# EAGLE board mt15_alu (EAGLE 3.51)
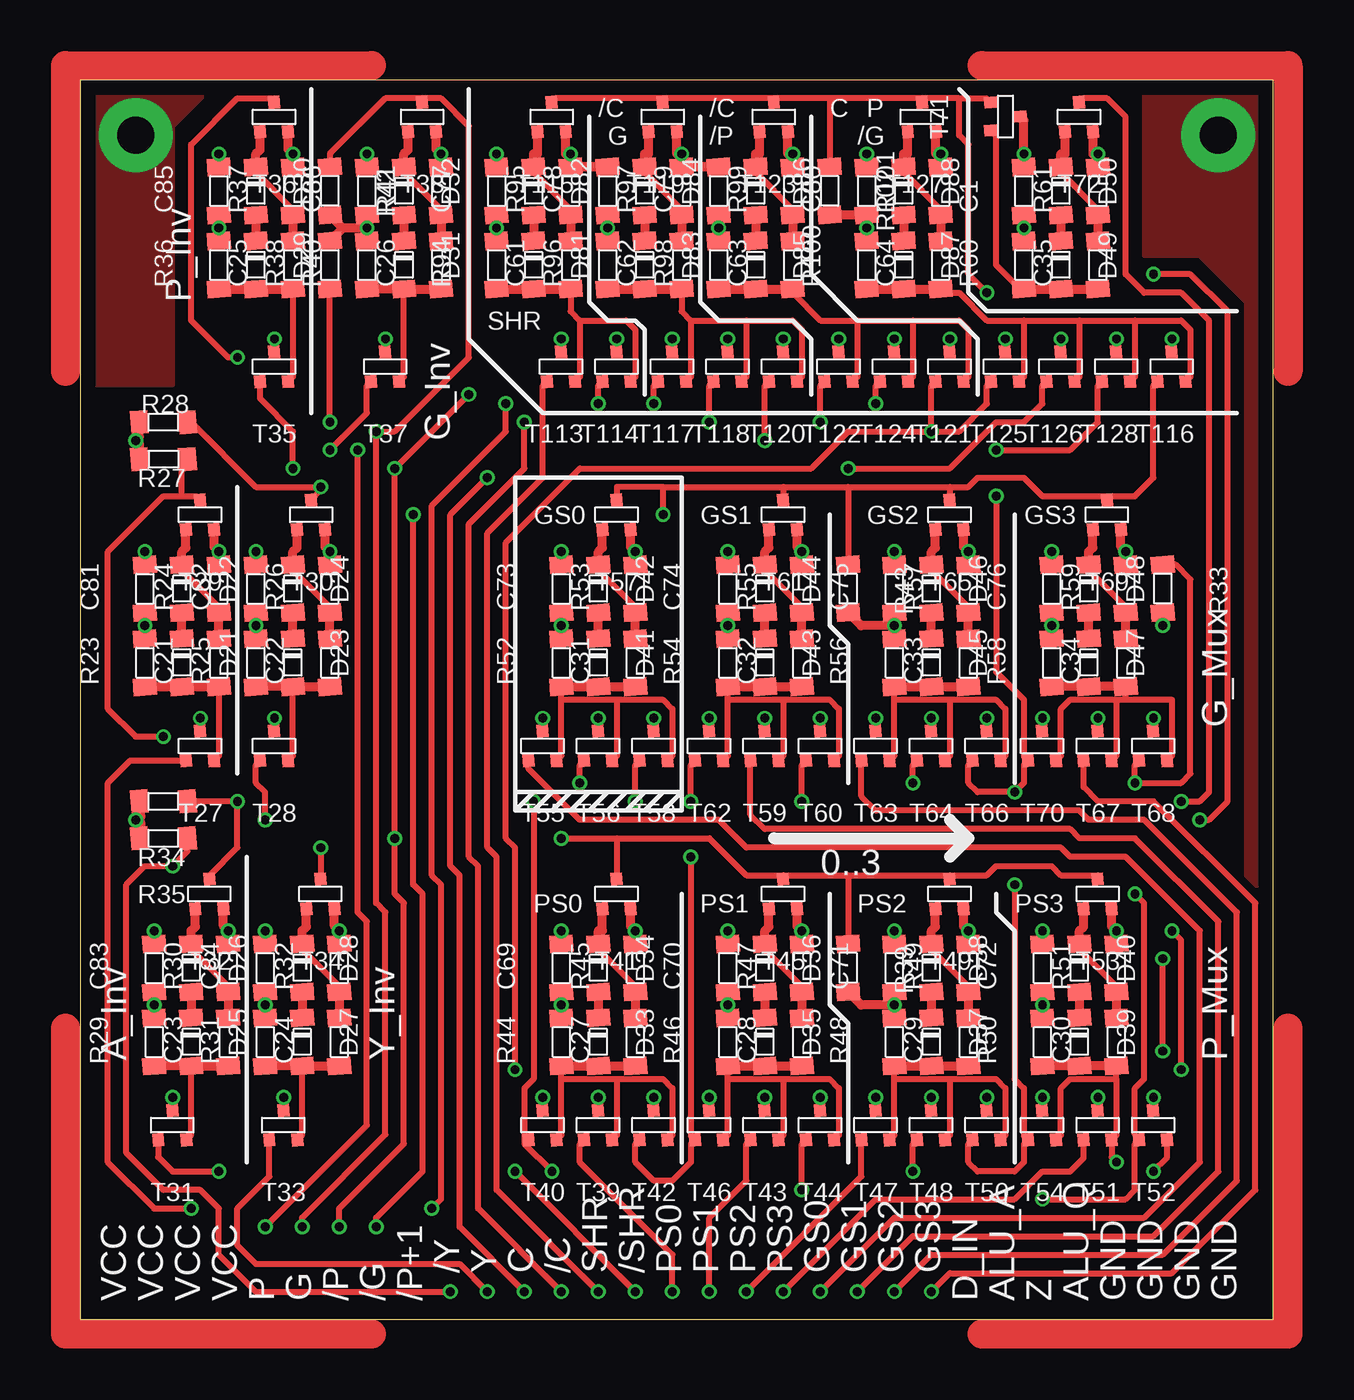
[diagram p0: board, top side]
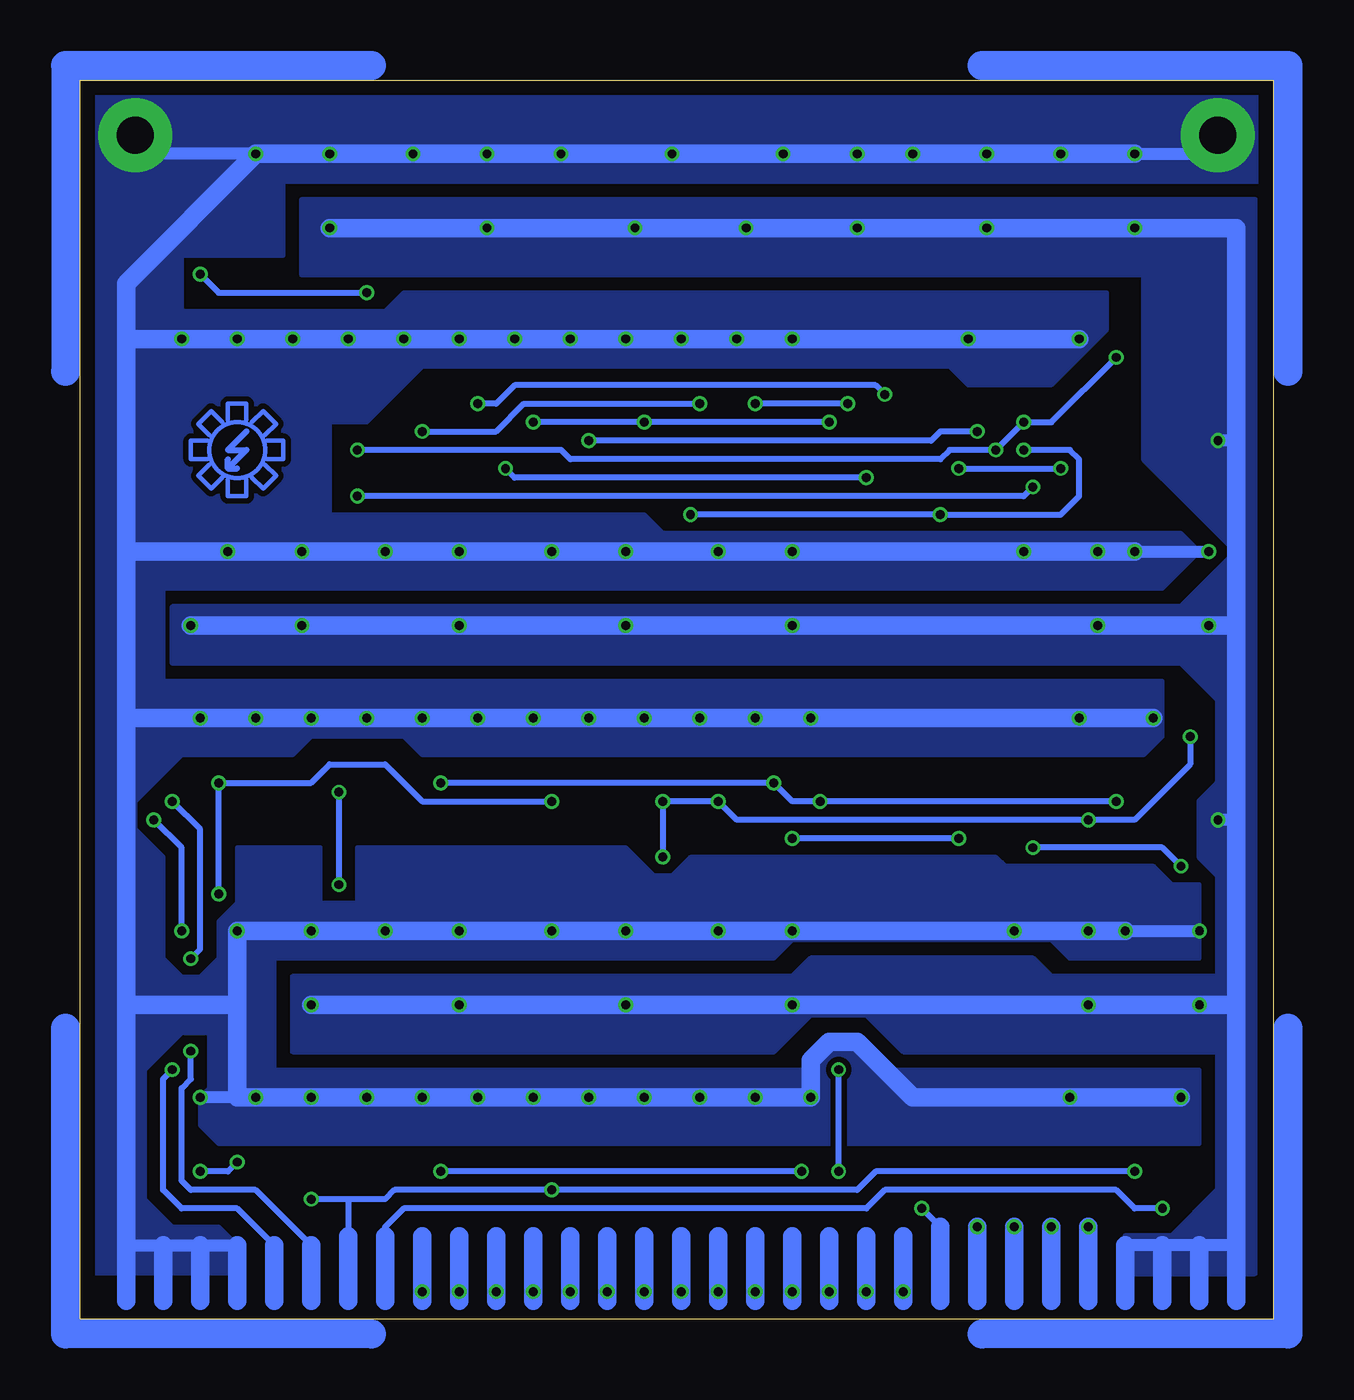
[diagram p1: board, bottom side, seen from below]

Size 81.89 x 85.08 mm. Coordinates in mm from the lower left corner, seen from the top.
Outline: 0,0 81.89,0 81.89,85.08 0,85.08 0,0
Copper layers used: Top, Bottom

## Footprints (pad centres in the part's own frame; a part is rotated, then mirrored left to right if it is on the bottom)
04 = smd 1.194 x 1.6 rotated 4.4:  1.651,0 | smd 1.194 x 1.6 rotated 4.3:  -1.651,0
04D = smd 1.194 x 1.6 rotated 4.3:  1.651,0 | smd 1.194 x 1.6 rotated 4.4:  -1.651,0
T-23 = smd 0.787 x 0.889 rotated 4.4:  0.991,1.016 | smd 0.787 x 0.889 rotated 4.3:  -0.94,1.016 | smd 0.787 x 0.889 rotated 4.5:  0.025,-1.016

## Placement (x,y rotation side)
C1  100n  [04]  64.77,77.47 90 top
C21  1n  [04]  9.53,45.09 90 top
C22  1n  [04]  17.14,45.09 90 top
C23  1n  [04]  10.16,19.05 90 top
C24  1n  [04]  17.78,19.05 90 top
C25  1n  [04]  14.61,72.39 90 top
C26  1n  [04]  24.77,72.39 90 top
C27  1n  [04]  38.1,19.05 90 top
C28  1n  [04]  49.53,19.05 90 top
C29  1n  [04]  60.96,19.05 90 top
C30  1n  [04]  71.12,19.05 90 top
C31  1n  [04]  38.1,45.09 90 top
C32  1n  [04]  49.53,45.09 90 top
C33  1n  [04]  60.96,45.09 90 top
C34  1n  [04]  71.75,45.09 90 top
C35  1n  [04]  69.85,72.39 90 top
C61  1n  [04]  33.66,72.39 90 top
C62  1n  [04]  41.27,72.39 90 top
C63  1n  [04]  48.9,72.39 90 top
C64  1n  [04]  59.05,72.39 90 top
C69  100n  [04]  33.02,24.13 90 top
C70  100n  [04]  44.45,24.13 90 top
C71  100n  [04]  55.88,24.13 90 top
C72  100n  [04]  66.04,24.13 90 top
C73  100n  [04]  33.02,50.16 90 top
C74  100n  [04]  44.45,50.16 90 top
C75  100n  [04]  55.88,50.16 90 top
C76  100n  [04]  66.67,50.16 90 top
C77  100n  [04]  28.57,77.47 90 top
C78  100n  [04]  36.2,77.47 90 top
C79  100n  [04]  43.81,77.47 90 top
C80  100n  [04]  53.98,77.47 90 top
C81  100n  [04]  4.45,50.16 90 top
C82  100n  [04]  12.06,50.16 90 top
C83  100n  [04]  5.08,24.13 90 top
C84  100n  [04]  12.7,24.13 90 top
C85  100n  [04]  9.53,77.47 90 top
C86  100n  [04]  19.68,77.47 90 top
D21  1N4148  [04D]  6.99,45.09 270 top
D22  1N4148  [04D]  6.99,50.16 270 top
D23  1N4148  [04D]  14.61,45.09 270 top
D24  1N4148  [04D]  14.61,50.16 270 top
D25  1N4148  [04D]  7.62,19.05 270 top
D26  1N4148  [04D]  7.62,24.13 270 top
D27  1N4148  [04D]  15.24,19.05 270 top
D28  1N4148  [04D]  15.24,24.13 270 top
D29  1N4148  [04D]  12.06,72.39 270 top
D30  1N4148  [04D]  12.06,77.47 270 top
D31  1N4148  [04D]  22.23,72.39 270 top
D32  1N4148  [04D]  22.23,77.47 270 top
D33  1N4148  [04D]  35.56,19.05 270 top
D34  1N4148  [04D]  35.56,24.13 270 top
D35  1N4148  [04D]  46.99,19.05 270 top
D36  1N4148  [04D]  46.99,24.13 270 top
D37  1N4148  [04D]  58.42,19.05 270 top
D38  1N4148  [04D]  58.42,24.13 270 top
D39  1N4148  [04D]  68.58,19.05 270 top
D40  1N4148  [04D]  68.58,24.13 270 top
D41  1N4148  [04D]  35.56,45.09 270 top
D42  1N4148  [04D]  35.56,50.16 270 top
D43  1N4148  [04D]  46.99,45.09 270 top
D44  1N4148  [04D]  46.99,50.16 270 top
D45  1N4148  [04D]  58.42,45.09 270 top
D46  1N4148  [04D]  58.42,50.16 270 top
D47  1N4148  [04D]  69.22,45.09 270 top
D48  1N4148  [04D]  69.22,50.16 270 top
D49  1N4148  [04D]  67.31,72.39 270 top
D50  1N4148  [04D]  67.31,77.47 270 top
D81  1N4148  [04D]  31.11,72.39 270 top
D82  1N4148  [04D]  31.11,77.47 270 top
D83  1N4148  [04D]  38.73,72.39 270 top
D84  1N4148  [04D]  38.73,77.47 270 top
D85  1N4148  [04D]  46.35,72.39 270 top
D86  1N4148  [04D]  46.35,77.47 270 top
D87  1N4148  [04D]  56.52,72.39 270 top
D88  1N4148  [04D]  56.52,77.47 270 top
R23  390  [04]  4.45,45.09 90 top
R24  820  [04]  9.53,50.16 90 top
R25  390  [04]  12.06,45.09 90 top
R26  820  [04]  17.14,50.16 90 top
R27  330  [04]  5.71,61.59 180 top
R28  330  [04]  5.71,59.05 0 top
R29  390  [04]  5.08,19.05 90 top
R30  820  [04]  10.16,24.13 90 top
R31  390  [04]  12.7,19.05 90 top
R32  820  [04]  17.78,24.13 90 top
R33  330  [04]  74.3,50.16 270 top
R34  330  [04]  5.71,35.56 180 top
R35  330  [04]  5.71,33.02 180 top
R36  390  [04]  9.53,72.39 90 top
R37  820  [04]  14.61,77.47 90 top
R38  330  [04]  17.14,72.39 90 top
R39  330  [04]  52.7,24.13 270 top
R40  390  [04]  19.68,72.39 90 top
R41  820  [04]  24.77,77.47 90 top
R42  330  [04]  17.14,77.47 270 top
R43  330  [04]  52.7,50.16 270 top
R44  390  [04]  33.02,19.05 90 top
R45  820  [04]  38.1,24.13 90 top
R46  390  [04]  44.45,19.05 90 top
R47  820  [04]  49.53,24.13 90 top
R48  390  [04]  55.88,19.05 90 top
R49  820  [04]  60.96,24.13 90 top
R50  390  [04]  66.04,19.05 90 top
R51  820  [04]  71.12,24.13 90 top
R52  390  [04]  33.02,45.09 90 top
R53  820  [04]  38.1,50.16 90 top
R54  390  [04]  44.45,45.09 90 top
R55  820  [04]  49.53,50.16 90 top
R56  390  [04]  55.88,45.09 90 top
R57  820  [04]  60.96,50.16 90 top
R58  390  [04]  66.67,45.09 90 top
R59  820  [04]  71.75,50.16 90 top
R60  390  [04]  64.77,72.39 90 top
R61  820  [04]  69.85,77.47 90 top
R94  390  [04]  28.57,72.39 90 top
R95  820  [04]  33.66,77.47 90 top
R96  390  [04]  36.2,72.39 90 top
R97  820  [04]  41.27,77.47 90 top
R98  390  [04]  43.81,72.39 90 top
R99  820  [04]  48.9,77.47 90 top
R100  390  [04]  53.98,72.39 90 top
R101  820  [04]  59.05,77.47 90 top
R102  330  [04]  51.44,77.47 270 top
T27  BC857  [T-23]  8.26,39.37 180 top
T28  BC857  [T-23]  13.34,39.37 180 top
T29  BC847  [T-23]  8.26,55.24 180 top
T30  BC847  [T-23]  15.88,55.24 180 top
T31  BC857  [T-23]  6.35,13.34 180 top
T32  BC847  [T-23]  8.89,29.21 180 top
T33  BC857  [T-23]  13.97,13.34 180 top
T34  BC847  [T-23]  16.51,29.21 180 top
T35  BC857  [T-23]  13.34,65.41 180 top
T36  BC847  [T-23]  13.34,82.55 180 top
T37  BC857  [T-23]  20.95,65.41 180 top
T38  BC847  [T-23]  23.5,82.55 180 top
T39  BC857  [T-23]  35.56,13.34 180 top
T40  BC857  [T-23]  31.75,13.34 180 top
T41  BC847  [T-23]  36.83,29.21 180 top
T42  BC857  [T-23]  39.37,13.34 180 top
T43  BC857  [T-23]  46.99,13.34 180 top
T44  BC857  [T-23]  50.8,13.34 180 top
T45  BC847  [T-23]  48.26,29.21 180 top
T46  BC857  [T-23]  43.18,13.34 180 top
T47  BC857  [T-23]  54.61,13.34 180 top
T48  BC857  [T-23]  58.42,13.34 180 top
T49  BC847  [T-23]  59.69,29.21 180 top
T50  BC857  [T-23]  62.23,13.34 180 top
T51  BC857  [T-23]  69.85,13.34 180 top
T52  BC857  [T-23]  73.66,13.34 180 top
T53  BC847  [T-23]  69.85,29.21 180 top
T54  BC857  [T-23]  66.04,13.34 180 top
T55  BC857  [T-23]  31.75,39.37 180 top
T56  BC857  [T-23]  35.56,39.37 180 top
T57  BC847  [T-23]  36.83,55.24 180 top
T58  BC857  [T-23]  39.37,39.37 180 top
T59  BC857  [T-23]  46.99,39.37 180 top
T60  BC857  [T-23]  50.8,39.37 180 top
T61  BC847  [T-23]  48.26,55.24 180 top
T62  BC857  [T-23]  43.18,39.37 180 top
T63  BC857  [T-23]  54.61,39.37 180 top
T64  BC857  [T-23]  58.42,39.37 180 top
T65  BC847  [T-23]  59.69,55.24 180 top
T66  BC857  [T-23]  62.23,39.37 180 top
T67  BC857  [T-23]  69.85,39.37 180 top
T68  BC857  [T-23]  73.66,39.37 180 top
T69  BC847  [T-23]  70.48,55.24 180 top
T70  BC857  [T-23]  66.04,39.37 180 top
T71  BC857  [T-23]  63.5,82.55 90 top
T72  BC847  [T-23]  68.58,82.55 180 top
T113  BC857  [T-23]  33.02,65.41 180 top
T114  BC857  [T-23]  36.83,65.41 180 top
T115  BC847  [T-23]  32.38,82.55 180 top
T116  BC857  [T-23]  74.93,65.41 180 top
T117  BC857  [T-23]  40.64,65.41 180 top
T118  BC857  [T-23]  44.45,65.41 180 top
T119  BC847  [T-23]  40.01,82.55 180 top
T120  BC857  [T-23]  48.26,65.41 180 top
T121  BC857  [T-23]  59.69,65.41 180 top
T122  BC857  [T-23]  52.07,65.41 180 top
T123  BC847  [T-23]  47.62,82.55 180 top
T124  BC857  [T-23]  55.88,65.41 180 top
T125  BC857  [T-23]  63.5,65.41 180 top
T126  BC857  [T-23]  67.31,65.41 180 top
T127  BC847  [T-23]  57.78,82.55 180 top
T128  BC857  [T-23]  71.12,65.41 180 top
U$1  []  71.12,59.69 0 bottom

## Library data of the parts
C1 C21-C35 C61-C64 C69-C86 D21-D50 D81-D88 R23-R61 R94-R102 = DISCRETE
T27 T28 T31 T33 T35 T37 T39 T40 T42-T44 T46-T48 T50-T52 T54-T56 T58-T60 T62-T64 T66-T68 T70 T71 T113 T114 T116-T118 T120-T122 T124-T126 T128 = PNP
T29 T30 T32 T34 T36 T38 T41 T45 T49 T53 T57 T61 T65 T69 T72 T115 T119 T123 T127 = NPN
U$1 = TAF

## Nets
!ALU_A: R34. T32. T40. T48. T56. T64.
!ALU_D: R28. T28. T29. T42. T46. T58. T62.
!C: T118. T122.
!G: R43. T37. T57. T61. T65. T69. T116.
!P: R39. T35. T41. T45. T49. T53. T124.
!P+1: T114.
!SHR: T117. T121. T125.
!Y: R35. T34.
ALU_A: R33. T31. T44. T52. T60. T68.
ALU_D: R27. T30. T50. T54. T66. T70.
ALU_Q: R102. T71. T115. T119. T123. T127.
C: T126.
D_IN: T27.
G: R42. T38. T120.
GND: C1. C69. C70. C71. C72. C73. C74. C75. C76. C77. C78. C79. C80. C81. C82. C83. C84. C85. C86. R24. R26. R30. R32. R37. R41. R45. R47. R49. R51. R53. R55. R57. R59. R61. R95. R97. R99. R101. T27. T28. T29. T30. T31. T32. T33. T34. T35. T36. T37. T38. T39. T40. T41. T42. T43. T44. T45. T46. T47. T48. T49. T50. T51. T52. T53. T54. T55. T56. T57. T58. T59. T60. T61. T62. T63. T64. T65. T66. T67. T68. T69. T70. T71. T72. T113. T114. T115. T116. T117. T118. T119. T120. T121. T122. T123. T124. T125. T126. T127. T128.
GS0: T55.
GS1: T59.
GS2: T63.
GS3: T67.
N$45: C22. D23. R25. T28.
N$46: C21. D21. R23. T27.
N$47: D21. D22.
N$48: C21. D22. R24. T29.
N$49: D23. D24.
N$50: C22. D24. R26. T30.
N$51: C23. D25. R29. T31.
N$52: D25. D26.
N$53: C23. D26. R30. T32.
N$54: C24. D27. R31. T33.
N$55: D27. D28.
N$56: C24. D28. R32. T34.
N$57: C25. D29. R36. T35.
N$58: D29. D30.
N$59: C25. D30. R37. T36.
N$60: C26. D31. R40. T37.
N$61: D31. D32.
N$62: C26. D32. R41. T38.
N$63: C27. D33. R44. T39. T40. T42.
N$64: D33. D34.
N$65: C27. D34. R45. T41.
N$66: C28. D35. R46. T43. T44. T46.
N$67: D35. D36.
N$68: C28. D36. R47. T45.
N$69: C29. D37. R48. T47. T48. T50.
N$70: D37. D38.
N$71: C29. D38. R49. T49.
N$72: C30. D39. R50. T51. T52. T54.
N$73: D39. D40.
N$74: C30. D40. R51. T53.
N$75: C31. D41. R52. T55. T56. T58.
N$76: D41. D42.
N$77: C31. D42. R53. T57.
N$78: C32. D43. R54. T59. T60. T62.
N$79: D43. D44.
N$80: C32. D44. R55. T61.
N$81: C33. D45. R56. T63. T64. T66.
N$82: D45. D46.
N$83: C33. D46. R57. T65.
N$84: C34. D47. R58. T67. T68. T70.
N$85: D47. D48.
N$86: C34. D48. R59. T69.
N$87: C35. D49. R60. T71.
N$92: D49. D50.
N$141: C61. D81. R94. T113. T114.
N$142: D81. D82.
N$143: C61. D82. R95. T115.
N$144: C62. D83. R96. T117. T118. T120.
N$145: D83. D84.
N$146: C62. D84. R97. T119.
N$147: C63. D85. R98. T121. T122. T124.
N$148: D85. D86.
N$149: C63. D86. R99. T123.
N$150: C64. D87. R100. T116. T125. T126. T128.
N$151: D87. D88.
N$152: C64. D88. R101. T127.
N$153: C35. D50. R61. T72.
P: R38. T36. T128.
PS0: T39.
PS1: T43.
PS2: T47.
PS3: T51.
SHR: T113.
VCC: C1. C69. C70. C71. C72. C73. C74. C75. C76. C77. C78. C79. C80. C81. C82. C83. C84. C85. C86. R23. R25. R27. R28. R29. R31. R33. R34. R35. R36. R38. R39. R40. R42. R43. R44. R46. R48. R50. R52. R54. R56. R58. R60. R94. R96. R98. R100. R102.
Y: T33.
Z: T72.

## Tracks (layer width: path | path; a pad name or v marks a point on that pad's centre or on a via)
!ALU_A  (via drill 0.61 pad 1.02)
  Top 0.406: 34.57,38.35 34.29,38.08 v34.29,36.83 | 57.43,38.35 57.15,38.08 v57.15,36.83 | 57.43,12.32 57.15,12.04 v57.15,10.16 | T32. 8.87,30.45 10.79,32.38 v10.79,35.56 R34. | 30.48,12.06 v32.38,10.16 | v31.11,35.56 31.11,16.51 30.48,15.88 30.48,12.06 | 30.76,12.32 30.73,12.32 30.48,12.06
  Bottom 0.406: v57.15,36.83 v34.29,36.83 33.02,35.56 v31.11,35.56 v10.79,35.56 | v32.38,10.16 v57.15,10.16
!ALU_D  (via drill 0.61 pad 1.02)
  Top 0.406: 42.19,38.35 41.91,38.08 v41.91,35.56 | 38.38,38.35 38.1,38.08 v38.1,35.56 | 12.34,38.35 12.06,38.08 12.06,36.83 12.7,36.2 v12.7,34.29 | 38.38,12.32 38.1,12.04 38.1,10.79 39.37,9.53 40.64,9.53 41.91,10.79 41.91,12.04 42.19,12.32 41.91,12.6 v41.91,31.75 | v5.71,40.01 3.81,40.01 1.91,41.91 1.91,52.7 5.71,56.52 6.99,56.52 | T29. 7.98,56.52 6.99,56.52 | 7.37,59.05 6.99,58.67 6.99,56.52
  Bottom 0.406: v41.91,31.75 v41.91,35.56 v38.1,35.56 36.83,34.29 v12.7,34.29 9.53,34.29 5.71,38.1 v5.71,40.01
!C  (via drill 0.61 pad 1.02)
  Top 0.406: 43.46,64.39 43.18,64.11 v43.18,61.59 | 51.08,64.39 50.8,64.11 v50.8,61.59 | v33.02,1.91 27.3,7.62 27.3,31.11 26.67,31.75 26.67,54.61 30.48,58.42 v30.48,61.59
  Bottom 0.406: v50.8,61.59 v43.18,61.59 v30.48,61.59
  Bottom 1.27: 33.02,1.27 v33.02,1.91 33.02,5.71
!G  (via drill 0.61 pad 1.02)
  Top 0.406: 48.26,57.15 52.7,57.15 | 52.7,57.15 59.69,57.15 | 40.01,57.15 36.83,57.15 36.83,56.29 T57. | v40.01,55.24 40.01,57.15 | 40.01,57.15 48.26,57.15 | T61. 48.26,56.29 48.26,57.15 | T65. 59.69,56.29 59.69,57.15 | T69. 70.48,56.29 70.48,56.52 | 59.69,57.15 60.96,57.15 61.59,57.78 64.77,57.78 66.04,56.52 70.48,56.52 | 73.94,64.39 73.66,64.11 73.66,57.78 72.39,56.52 70.48,56.52 | v20.32,6.35 20.32,6.99 23.5,10.16 23.5,29.21 22.86,29.84 v22.86,55.24 | 52.7,57.15 R43. | 19.96,64.39 19.68,64.11 19.68,62.23 v17.14,59.69
  Bottom 0.406: v40.01,55.24 v22.86,55.24 14.61,55.24 13.34,56.52 13.34,59.05 13.97,59.69 v17.14,59.69
  Bottom 1.27: 20.32,1.27 v20.32,6.35
!P  (via drill 0.61 pad 1.02)
  Top 0.406: T41. 36.83,30.25 36.83,33.02 | T53. 69.85,30.25 69.85,30.48 67.31,30.48 66.67,31.11 62.87,31.11 62.23,30.48 59.69,30.48 | 36.83,33.02 43.18,33.02 45.72,30.48 48.26,30.48 | 48.26,30.48 52.7,30.48 | 52.7,30.48 59.69,30.48 | T49. 59.69,30.25 59.69,30.48 | T45. 48.26,30.25 48.26,30.48 | 52.7,30.48 R39. | v17.78,6.35 17.78,7.62 22.23,12.06 22.23,28.57 21.59,29.21 v21.59,33.02 v21.59,58.42 v26.67,63.5 | v33.02,33.02 36.83,33.02 | 12.34,64.49 12.34,64.39 12.34,63.22 14.61,60.96 v14.61,58.42 | 54.89,64.39 54.61,64.11 v54.61,62.87
  Bottom 0.406: v21.59,33.02 v33.02,33.02 | v21.59,58.42 v14.61,58.42 | v26.67,63.5 27.3,64.14 52.07,64.14 53.34,62.87 v54.61,62.87
  Bottom 1.27: 17.78,1.27 v17.78,6.35
!P+1  (via drill 0.61 pad 1.02)
  Top 0.406: v24.13,7.62 24.77,8.26 24.77,29.84 24.13,30.48 24.13,55.88 29.21,60.96 v29.21,62.87 | 35.56,64.11 35.84,64.39 | v35.56,62.87 35.56,64.11 | 35.56,64.11 35.56,64.14
  Bottom 0.406: 22.86,6.35 v24.13,7.62 | v29.21,62.87 v35.56,62.87
  Bottom 1.27: 22.86,1.27 22.86,6.35
!SHR  (via drill 0.61 pad 1.02)
  Top 0.406: 39.65,64.39 39.37,64.11 v39.37,62.87 | 58.7,64.39 58.42,64.11 v58.42,60.96 | 62.51,64.39 62.23,64.11 62.23,62.87 60.33,60.96 v58.42,60.96 | v29.84,10.16 v38.1,1.91 | v29.84,17.14 29.84,32.38 29.21,33.02 29.21,53.34 34.29,58.42 50.16,58.42 52.7,60.96 v58.42,60.96
  Bottom 0.406: v58.42,60.96 53.34,60.96 51.44,62.87 v39.37,62.87 | v29.84,10.16 v29.84,17.14
  Bottom 1.27: 38.1,1.27 v38.1,1.91 38.1,5.71
!Y  (via drill 0.61 pad 1.02)
  Top 0.406: T34. 16.51,30.25 v16.51,32.38 | v25.4,1.91 12.06,1.91 9.53,4.45 9.53,7.62 8.26,8.89 5.71,8.89 3.17,11.43 3.17,29.84 4.45,31.11 v6.35,31.11 7.37,32.13 R35.
  Bottom 0.406: v6.35,31.11 7.62,32.38 v16.51,32.38
  Bottom 1.27: 25.4,1.27 v25.4,1.91 25.4,5.71
ALU_A  (via drill 0.61 pad 1.02)
  Top 0.406: 49.81,38.35 49.53,38.08 v49.53,35.56 | 72.67,38.35 72.39,38.08 v72.39,36.83 75.56,36.83 76.2,37.47 76.2,50.8 75.18,51.82 R33. | 49.81,12.32 49.53,12.04 v49.53,8.89 | v66.04,8.26 71.75,8.26 72.39,8.89 72.39,12.04 72.67,12.32 72.67,12.42 72.39,12.7 72.39,15.88 73.03,16.51 73.03,28.57 v72.39,29.21 | v9.53,10.16 6.35,10.16 5.36,11.15 5.36,12.32
  Bottom 0.406: v49.53,35.56 58.42,35.56 60.96,38.1 64.77,38.1 66.04,36.83 v72.39,36.83 v72.39,29.21 | 63.5,8.26 60.96,8.26 60.33,8.89 v49.53,8.89 28.57,8.89 27.3,10.16 v9.53,10.16 | 63.5,8.26 v66.04,8.26 | 63.5,8.26 63.5,5.71
  Bottom 1.27: 63.5,5.71 63.5,1.27
ALU_D  (via drill 0.61 pad 1.02)
  Top 0.406: 61.24,38.35 60.96,38.08 60.96,36.83 61.59,36.2 v64.14,36.2 64.77,36.83 64.77,38.08 65.05,38.35 64.77,38.63 64.77,42.55 62.87,44.45 v62.87,56.52 | 61.24,12.32 60.96,12.04 60.96,10.79 61.59,10.16 64.14,10.16 64.77,10.79 64.77,12.04 65.05,12.32 64.77,12.6 64.77,15.88 64.14,16.51 v64.14,29.84 | R27. 7.62,61.59 12.06,57.15 v16.51,57.15 | v16.51,57.15 16.48,57.12 | T30. 16.51,56.92 v16.51,57.15
  Bottom 0.406: v64.14,36.2 v64.14,29.84 | v62.87,56.52 17.14,56.52 v16.51,57.15
ALU_Q  (via drill 0.61 pad 1.02)
  Top 0.406: T115. 32.61,83.82 40.01,83.82 | 47.62,83.82 40.01,83.82 | 51.44,83.82 47.62,83.82 | 51.44,83.82 R102. | T119. 40.01,83.59 40.01,83.82 | T123. 47.62,83.59 47.62,83.82 | 57.78,83.82 51.44,83.82 | T127. 57.76,83.8 57.78,83.82 | 60.33,83.82 57.78,83.82 | 60.33,83.82 60.33,81.28 60.96,80.64 60.96,71.75 v62.23,70.48 | 62.48,83.54 62.2,83.82 60.33,83.82 | v73.66,71.75 76.2,71.75 78.74,69.22 78.74,35.56 77.47,34.29 v76.83,34.29 | v74.93,26.67 75.56,26.04 v75.56,17.14
  Bottom 0.406: v62.23,70.48 72.39,70.48 v73.66,71.75 | v76.83,34.29 74.93,32.38 v74.93,26.67 | v75.56,17.14 76.2,16.51 76.2,8.89 74.93,7.62 71.12,7.62 68.58,5.08
  Bottom 1.27: 68.58,1.27 68.58,5.08
C  (via drill 0.61 pad 1.02)
  Top 0.406: v30.48,1.91 26.04,6.35 26.04,30.48 25.4,31.11 25.4,55.24 v27.94,57.78 | 66.32,64.39 66.04,64.11 66.04,62.87 64.77,61.59 62.87,61.59 59.69,58.42 v52.7,58.42
  Bottom 0.406: v27.94,57.78 52.07,57.78 v52.7,58.42
  Bottom 1.27: 30.48,1.27 v30.48,1.91 30.48,5.71
D_IN  (via drill 0.61 pad 1.02)
  Top 0.406: v7.62,7.62 5.08,7.62 1.91,10.79 1.91,36.83 3.43,38.35 7.26,38.35
  Bottom 0.406: 60.96,5.71 60.96,6.35 59.69,7.62 27.94,7.62 26.67,8.89 10.79,8.89 9.53,7.62 v7.62,7.62
  Bottom 1.27: 60.96,5.71 60.96,1.27
G  (via drill 0.61 pad 1.02)
  Top 0.406: 47.27,64.39 46.99,64.11 v46.99,60.33 | R42. 17.14,80.01 20.95,83.82 23.5,83.82 | T38. 23.5,83.59 23.5,83.82 | 23.5,83.82 24.77,83.82 26.67,81.92 26.67,66.04 21.59,60.96 v20.32,60.96 20.32,28.57 20.95,27.94 20.95,12.7 15.24,6.99 v15.24,6.35
  Bottom 0.406: v20.32,60.96 22.86,60.96 23.5,60.33 v46.99,60.33
  Bottom 1.27: 15.24,1.27 v15.24,6.35
GND  (via drill 0.61 pad 1.02, 2.54 pad 5.08)
  Top 0.61: 33.33,81.53 33.33,80.01 v33.66,80.01 33.66,79.12 | 40.95,81.53 40.95,80.01 v41.27,80.01 41.27,79.12 | 48.56,81.53 48.56,80.01 v48.9,80.01 48.9,79.12 | 59.05,79.12 v59.05,80.01 58.73,80.01 58.73,81.53 | 69.52,81.53 69.52,80.01 v69.85,80.01 69.85,79.12 | 64.77,79.12 v64.77,80.01 64.77,82.32 T71. | v28.57,80.01 28.57,79.12 | T113. 33.02,66.45 v33.02,67.31 | T114. 36.83,66.45 v36.83,67.31 | T117. 40.64,66.45 v40.64,67.31 | T118. 44.45,66.45 v44.45,67.31 | T120. 48.26,66.45 v48.26,67.31 | T121. 59.69,66.45 v59.69,67.31 | T122. 52.07,66.45 v52.07,67.31 | T124. 55.88,66.45 v55.88,67.31 | T116. 74.93,66.45 v74.93,67.31 | T128. 71.12,66.45 v71.12,67.31 | T126. 67.31,66.45 v67.31,67.31 | T125. 63.5,66.45 v63.5,67.31 | v33.02,52.7 33.02,51.82 | 37.77,54.23 37.77,53.03 v38.1,52.7 38.1,51.82 | v44.45,52.7 44.45,51.82 | 49.2,54.23 49.2,53.03 v49.53,52.7 49.53,51.82 | v55.88,52.7 55.88,51.82 | 60.63,54.23 60.63,53.03 v60.96,52.7 60.96,51.82 | 71.42,54.23 71.42,53.03 v71.75,52.7 71.75,51.82 | v66.67,52.7 66.67,51.82 | 37.77,28.19 37.77,27 v38.1,26.67 38.1,25.78 | 49.2,28.19 49.2,27 v49.53,26.67 49.53,25.78 | v44.45,26.67 44.45,25.78 | v33.02,26.67 33.02,25.78 | v55.88,26.67 55.88,25.78 | 60.63,28.19 60.63,27 v60.96,26.67 60.96,25.78 | 70.79,28.19 70.79,27 v71.12,26.67 71.12,25.78 | v66.04,26.67 66.04,25.78 | T55. 31.75,40.41 v31.75,41.27 | T56. 35.56,40.41 v35.56,41.27 | T58. 39.37,40.41 v39.37,41.27 | T62. 43.18,40.41 v43.18,41.27 | T59. 46.99,40.41 v46.99,41.27 | T60. 50.8,40.41 v50.8,41.27 | T63. 54.61,40.41 v54.61,41.27 | T64. 58.42,40.41 v58.42,41.27 | T66. 62.23,40.41 v62.23,41.27 | T68. 73.66,40.41 v73.66,41.27 | T70. 66.04,40.41 v66.04,41.27
  Top 0.61: T67. 69.85,40.41 v69.85,41.27 | T52. 73.66,14.38 v73.66,15.24 | T51. 69.85,14.38 v69.85,15.24 | T54. 66.04,14.38 v66.04,15.24 | T50. 62.23,14.38 v62.23,15.24 | T48. 58.42,14.38 v58.42,15.24 | T47. 54.61,14.38 v54.61,15.24 | T44. 50.8,14.38 v50.8,15.24 | T43. 46.99,14.38 v46.99,15.24 | T46. 43.18,14.38 v43.18,15.24 | T42. 39.37,14.38 v39.37,15.24 | 9.83,28.19 9.83,27 v10.16,26.67 10.16,25.78 | v5.08,26.67 5.08,25.78 | v12.7,26.67 12.7,25.78 | 17.45,28.19 17.45,27 v17.78,26.67 17.78,25.78 | v4.45,52.7 4.45,51.82 | 9.2,54.23 9.2,53.03 v9.53,52.7 9.53,51.82 | v12.06,52.7 12.06,51.82 | 16.82,54.23 16.82,53.03 v17.14,52.7 17.14,51.82 17.14,51.44 | 14.28,81.53 14.28,80.34 v14.61,80.01 14.61,79.12 | v9.53,80.01 9.53,79.12 | v19.68,80.01 19.68,79.12 | 24.43,81.53 24.43,80.34 v24.77,80.01 24.77,79.12 | T31. 6.35,14.38 v6.35,15.24 | T33. 13.97,14.38 v13.97,15.24 | T27. 8.26,40.41 v8.26,41.27 | T28. 13.34,40.41 v13.34,41.27 | T35. 13.34,66.45 v13.34,67.31 | T37. 20.95,66.45 v20.95,67.31 | T40. 31.75,14.38 v31.75,15.24 | T39. 35.56,14.38 v35.56,15.24
  Top 0.635: 33.66,79.12 36.2,79.12 | 41.27,79.12 43.81,79.12 | v53.98,80.01 53.98,79.12
  Bottom 0.813: 71.12,15.24 v73.66,15.24 | v10.16,26.67 v5.08,26.67 | v9.53,52.7 v4.45,52.7 | 78.74,5.08 76.2,5.08 73.66,5.08 71.12,5.08 | v69.85,80.01 76.83,80.01 v78.11,81.28 | v3.81,81.28 5.08,80.01 v9.53,80.01
  Bottom 1.27: 78.74,67.31 v74.93,67.31 v71.12,67.31 v67.31,67.31 v63.5,67.31 v59.69,67.31 v55.88,67.31 v52.07,67.31 v48.26,67.31 v44.45,67.31 v40.64,67.31 v36.83,67.31 v33.02,67.31 v20.95,67.31 v13.34,67.31 | 78.74,67.31 78.74,71.12 v69.85,80.01 v64.77,80.01 v59.05,80.01 v53.98,80.01 v48.9,80.01 v41.27,80.01 v33.66,80.01 v28.57,80.01 v24.77,80.01 v19.68,80.01 v14.61,80.01 v9.53,80.01 | 78.74,41.27 v73.66,41.27 v69.85,41.27 v66.04,41.27 v62.23,41.27 v58.42,41.27 v54.61,41.27 v50.8,41.27 v46.99,41.27 v43.18,41.27 v39.37,41.27 v35.56,41.27 v31.75,41.27 v13.34,41.27 v8.26,41.27 | 78.74,41.27 78.74,52.7 | 78.74,52.7 78.74,67.31 | 78.74,52.7 v71.75,52.7 v66.67,52.7 v60.96,52.7 v55.88,52.7 v49.53,52.7 v44.45,52.7 v38.1,52.7 v33.02,52.7 v17.14,52.7 v12.06,52.7 v9.53,52.7 | 78.74,21.59 78.74,41.27 | v10.16,26.67 v12.7,26.67 v17.78,26.67 v33.02,26.67 v38.1,26.67 v44.45,26.67 v49.53,26.67 v55.88,26.67 v60.96,26.67 v66.04,26.67 v71.12,26.67 71.12,21.59 | v6.35,15.24 v13.97,15.24 24.77,15.24 28.57,19.05 30.48,19.05 31.75,17.78 v31.75,15.24 v35.56,15.24 v39.37,15.24 v43.18,15.24 v46.99,15.24 v50.8,15.24 v54.61,15.24 v58.42,15.24 v62.23,15.24 v66.04,15.24 v69.85,15.24 71.12,15.24 71.12,21.59 | 78.74,21.59 78.74,5.08 78.74,1.27 | 76.2,5.08 76.2,1.27 | 73.66,5.08 73.66,1.27 | 71.12,5.08 71.12,1.27 | 71.12,21.59 78.74,21.59
  pour Bottom (isolate 0.356): 81.28,84.45 81.28,3.17 71.12,3.17 71.12,5.08 72.39,6.35 75.56,6.35 77.47,8.26 77.47,17.14 74.93,19.68 73.03,19.68 73.03,15.88 73.66,15.24 73.66,13.34 72.39,12.06 5.08,12.06 5.08,17.14 26.67,17.14 27.94,18.41 30.48,18.41 31.75,17.14 68.58,17.14 68.58,24.77 34.29,24.77 33.02,26.04 15.24,26.04 13.97,24.77 5.08,24.77 5.08,29.84 6.99,29.84 8.26,31.11 18.41,31.11 19.05,31.75 40.01,31.75 41.27,30.48 42.55,30.48 44.45,32.38 62.87,32.38 62.87,28.57 65.41,28.57 65.41,32.38 71.12,32.38 71.12,28.57 72.39,27.3 72.39,24.77 73.66,23.5 74.93,23.5 76.2,24.77 76.2,31.75 78.11,33.66 78.11,35.56 74.93,38.73 67.31,38.73 66.04,40.01 59.69,40.01 58.42,38.73 8.89,38.73 7.62,40.01 7.62,43.81 76.2,43.81 76.2,50.16 7.62,50.16 5.08,52.7 6.35,53.98 41.91,53.98 43.18,55.24 64.77,55.24 64.77,61.59 62.23,61.59 58.42,65.41 22.23,65.41 20.95,64.14 15.24,64.14 11.43,67.94 11.43,70.48 59.69,70.48 60.96,69.22 74.93,69.22 74.93,73.03 67.94,73.03 67.94,78.11 0.64,78.11 0.64,84.45
  pour Top (isolate 0.356): 0.64,84.45 8.89,84.45 6.35,81.92 6.35,64.14 0.64,64.14
  pour Top (isolate 0.356): 81.28,84.45 73.03,84.45 73.03,73.03 76.83,73.03 80.01,69.85 80.01,30.48 81.28,29.21
GS0  (via drill 0.61 pad 1.02)
  Top 0.406: v50.8,1.91 55.88,6.99 73.03,6.99 76.83,10.79 76.83,26.67 71.75,31.75 67.94,31.75 67.31,32.38 45.72,32.38 43.81,34.29 34.29,34.29 30.76,37.82 30.76,38.35
  Bottom 1.27: 50.8,1.27 v50.8,1.91 50.8,5.71
GS1  (via drill 0.61 pad 1.02)
  Top 0.406: 46,38.35 46,34.65 46.99,33.66 67.94,33.66 68.58,33.02 72.39,33.02 78.11,27.3 78.11,10.16 73.66,5.71 57.15,5.71 v53.34,1.91
  Bottom 1.27: 53.34,1.27 v53.34,1.91 53.34,5.71
GS2  (via drill 0.61 pad 1.02)
  Top 0.406: 53.62,38.35 53.62,35.92 54.61,34.92 68.58,34.92 69.22,34.29 73.03,34.29 79.38,27.94 79.38,9.53 74.3,4.45 58.42,4.45 v55.88,1.91
  Bottom 1.27: 55.88,1.27 v55.88,1.91 55.88,5.71
GS3  (via drill 0.61 pad 1.02)
  Top 0.406: 68.86,38.35 68.86,36.55 69.85,35.56 73.66,35.56 80.64,28.57 80.64,8.89 74.93,3.17 59.69,3.17 v58.42,1.91
  Bottom 1.27: 58.42,1.27 v58.42,1.91 58.42,5.71
N$1
  Top 2: 20,-1 -1,-1 -1,20
N$2
  Top 2: 61.9,-1 82.89,-1 82.89,20
N$3
  Top 2: 20,86.08 -1,86.08 -1,65.08
N$4
  Top 2: 82.89,65.08 82.89,86.08 61.9,86.08
N$5
  Bottom 2: 20,-1 -1,-1 -1,20
N$6
  Bottom 2: 61.9,-1 82.89,-1 82.89,20
N$7
  Bottom 2: 20,86.08 -1,86.08 -1,65.08
N$8
  Bottom 2: 82.89,65.08 82.89,86.08 61.9,86.08
N$45
  Top 0.406: 14.28,38.35 14.61,38.68 14.61,43.43
  Top 0.61: R25. 14.61,43.43 C22.
N$46
  Top 0.406: 9.2,38.35 9.53,38.68 C21.
  Top 0.61: R23. 6.99,43.43 C21.
N$47
  Top 0.61: D21. 6.99,48.51
N$48
  Top 0.406: R24. 9.53,48.9 6.99,51.44
  Top 0.61: 9.53,46.74 R24. | 7.26,54.23 7.26,52.98 6.99,52.7 D22. 6.99,51.44
N$49
  Top 0.61: D23. 14.61,48.51
N$50
  Top 0.406: R26. 17.14,48.9 14.61,51.44 D24.
  Top 0.61: 17.14,46.74 R26. | 14.88,54.23 14.88,52.98 14.61,52.7 D24.
N$51
  Top 0.406: 7.29,12.32 7.62,12.65 7.62,17.4
  Top 0.61: R29. 7.62,17.4 C23.
N$52
  Top 0.61: 7.62,22.48 D25.
N$53
  Top 0.406: R30. 10.16,22.86 7.62,25.4 D26.
  Top 0.61: R30. 10.16,20.7 | 7.9,28.19 7.9,26.95 7.62,26.67 D26.
N$54
  Top 0.406: 14.91,12.32 15.24,12.65 15.24,17.4
  Top 0.61: R31. 15.24,17.4 C24.
N$55
  Top 0.61: 15.24,22.48 D27.
N$56
  Top 0.406: R32. 17.78,22.86 15.24,25.4 D28.
  Top 0.61: R32. 17.78,20.7 | 15.52,28.19 15.52,26.95 15.24,26.67 D28.
N$57
  Top 0.406: 14.28,64.39 14.61,64.72 C25.
  Top 0.61: R36. 12.06,70.74 C25.
N$58
  Top 0.61: 12.06,75.82 D29.
N$59
  Top 0.406: R37. 14.61,76.2 12.06,78.74 D30.
  Top 0.61: R37. 14.61,74.04 | 12.34,81.53 12.34,80.29 12.06,80.01 D30.
N$60
  Top 0.406: 21.89,64.39 22.23,64.72 22.23,70.74
  Top 0.61: R40. 22.23,70.74 C26.
N$61
  Top 0.61: 22.23,75.82 D31.
N$62
  Top 0.406: R41. 24.77,76.2 22.23,78.74 D32.
  Top 0.61: R41. 24.77,74.04 | 22.5,81.53 22.5,80.29 22.23,80.01 D32.
N$63
  Top 0.406: 33.02,12.7 33.02,16.51 | 33.02,16.51 R44. | 36.83,16.51 36.83,12.7 | 33.02,16.51 36.83,16.51 | 40.31,12.32 40.64,12.65 40.64,15.88 40.01,16.51 36.83,16.51 | 33.02,12.7 33.02,12.65 | 32.69,12.32 32.69,12.37 33.02,12.7 | 36.83,12.7 36.83,12.65 | 36.5,12.32 36.5,12.37 36.83,12.7
  Top 0.61: R44. 35.56,17.4 C27.
N$64
  Top 0.61: 35.56,22.48 D33.
N$65
  Top 0.406: R45. 38.1,22.86 35.56,25.4 D34.
  Top 0.61: R45. 38.1,20.7 | 35.84,28.19 35.84,26.67 35.56,26.67 D34.
N$66
  Top 0.406: 44.12,12.32 44.45,12.65 44.45,16.51 | 44.45,16.51 R46. | 47.93,12.32 48.26,12.65 48.26,16.51 | 44.45,16.51 48.26,16.51 | 51.74,12.32 52.07,12.65 52.07,15.88 51.44,16.51 48.26,16.51
  Top 0.61: R46. 46.99,17.4 C28.
N$67
  Top 0.61: 46.99,22.48 D35.
N$68
  Top 0.406: R47. 49.53,22.86 46.99,25.4 D36.
  Top 0.61: R47. 49.53,20.7 | 47.27,28.19 47.27,26.95 46.99,26.67 D36.
N$69
  Top 0.406: 55.55,12.32 55.88,12.65 55.88,16.51 | 55.88,16.51 R48. | 59.36,12.32 59.69,12.65 59.69,16.51 | 55.88,16.51 59.69,16.51 | 63.17,12.32 63.5,12.65 63.5,15.88 62.87,16.51 59.69,16.51
  Top 0.61: R48. 58.42,17.4 C29.
N$70
  Top 0.61: 58.42,22.48 D37.
N$71
  Top 0.406: R49. 60.96,22.86 58.42,25.4 D38.
  Top 0.61: R49. 60.96,20.7 | 58.7,28.19 58.7,26.95 58.42,26.67 D38.
N$72  (via drill 0.61 pad 1.02)
  Top 0.406: 66.98,12.32 67.31,12.65 67.31,15.88 67.94,16.51 71.12,16.51 | 71.12,16.51 71.12,12.65 70.79,12.32 70.79,11.12 v71.12,10.79 | 71.12,16.51 C30. | 74.6,12.32 74.6,11.1 v73.66,10.16
  Top 0.61: C30. 68.58,17.4 R50.
  Bottom 0.406: v73.66,10.16 71.75,10.16 v71.12,10.79
N$73
  Top 0.61: 68.58,22.48 D39.
N$74
  Top 0.406: R51. 71.12,22.86 68.58,25.4 D40.
  Top 0.61: R51. 71.12,20.7 | 68.86,28.19 68.86,26.95 68.58,26.67 D40.
N$75
  Top 0.406: 32.69,38.35 33.02,38.68 33.02,42.55 | 33.02,42.55 R52. | 36.5,38.35 36.83,38.68 36.83,42.55 | 33.02,42.55 36.83,42.55 | 40.31,38.35 40.64,38.68 40.64,41.91 40.01,42.55 36.83,42.55
  Top 0.61: R52. 35.56,43.43 C31.
N$76
  Top 0.61: D41. 35.56,48.51
N$77
  Top 0.406: R53. 38.1,48.9 35.56,51.44 D42.
  Top 0.61: 38.1,46.74 R53. | 35.84,54.23 35.84,52.98 35.56,52.7 D42.
N$78
  Top 0.406: 44.12,38.35 44.45,38.68 44.45,42.55 | 44.45,42.55 R54. | 47.93,38.35 48.26,38.68 48.26,42.55 | 44.45,42.55 48.26,42.55 | 51.74,38.35 52.07,38.68 52.07,41.91 51.44,42.55 48.26,42.55
  Top 0.61: R54. 46.99,43.43 C32.
N$79
  Top 0.61: D43. 46.99,48.51
N$80
  Top 0.406: R55. 49.53,48.9 46.99,51.44 D44.
  Top 0.61: 49.53,46.74 R55. | 47.27,54.23 47.27,52.98 46.99,52.7 D44.
N$81
  Top 0.406: 55.55,38.35 55.88,38.68 55.88,42.55 | 55.88,42.55 R56. | 59.36,38.35 59.69,38.68 59.69,42.55 | 55.88,42.55 59.69,42.55 | 63.17,38.35 63.5,38.68 63.5,41.91 62.87,42.55 59.69,42.55
  Top 0.61: R56. 58.42,43.43 C33.
N$82
  Top 0.61: D45. 58.42,48.51
N$83
  Top 0.406: D46. 58.42,51.44 60.96,48.9 R57.
  Top 0.61: 60.96,46.74 R57. | 58.7,54.23 58.7,52.98 58.42,52.7 D46.
N$84
  Top 0.406: 70.79,38.35 71.12,38.68 71.12,42.55 | 74.6,38.35 74.93,38.68 74.93,42.55 71.75,42.55 | 71.12,42.55 71.75,42.55 | 66.98,38.35 67.31,38.68 67.31,41.91 67.94,42.55 71.12,42.55 | 71.75,42.55 C34.
  Top 0.61: R58. 69.22,43.43 C34.
N$85
  Top 0.61: D47. 69.22,48.51
N$86
  Top 0.406: R59. 71.75,48.9 69.22,51.44 D48.
  Top 0.61: 71.75,46.74 R59. | 69.49,54.23 69.49,52.98 69.22,52.7 D48.
N$87
  Top 0.406: 62.48,81.61 62.87,81.23 62.87,72.39 64.52,70.74 R60.
  Top 0.61: R60. 67.31,70.74 C35.
N$92
  Top 0.61: 67.31,75.82 D49.
N$141
  Top 0.406: 33.96,64.39 34.29,64.72 34.29,68.58 | 37.77,64.39 38.1,64.72 38.1,67.94 37.47,68.58 34.29,68.58 | 34.29,68.58 33.66,69.22 C61.
  Top 0.61: R94. 31.11,70.74 C61.
N$142
  Top 0.61: 31.11,75.82 D81.
N$143
  Top 0.406: R95. 33.66,76.2 31.11,78.74 D82.
  Top 0.61: R95. 33.66,74.04 | 31.39,81.53 31.39,80.01 31.11,80.01 D82.
N$144
  Top 0.406: 41.58,64.39 41.91,64.72 41.91,68.58 | 45.39,64.39 45.72,64.72 45.72,68.58 | 41.91,68.58 41.27,69.22 C62. | 49.2,64.39 49.53,64.72 49.53,67.94 48.9,68.58 45.72,68.58 | 41.91,68.58 45.72,68.58
  Top 0.61: R96. 38.73,70.74 C62.
N$145
  Top 0.61: 38.73,75.82 D83.
N$146
  Top 0.406: R97. 41.27,76.2 38.73,78.74 D84.
  Top 0.61: R97. 41.27,74.04 | 39.01,81.53 39.01,80.01 38.73,80.01 D84.
N$147
  Top 0.406: 53.01,64.39 53.34,64.72 53.34,68.58 | 53.34,68.58 50.8,68.58 48.9,70.48 C63. | 56.82,64.39 57.15,64.72 57.15,68.58 | 53.34,68.58 57.15,68.58 | 60.63,64.39 60.96,64.72 60.96,67.94 60.33,68.58 57.15,68.58
  Top 0.61: R98. 46.35,70.74 C63.
N$148
  Top 0.61: 46.35,75.82 D85.
N$149
  Top 0.406: R99. 48.9,76.2 46.35,78.74 D86.
  Top 0.61: R99. 48.9,74.04 | 46.63,81.53 46.63,80.01 46.35,80.01 D86.
N$150
  Top 0.406: 64.44,64.39 64.77,64.72 64.77,68.58 | 64.77,68.58 62.23,68.58 60.33,70.48 59.05,70.48 C64. | 68.25,64.39 68.58,64.72 68.58,68.58 | 64.77,68.58 68.58,68.58 | 72.06,64.39 72.39,64.72 72.39,68.58 | 68.58,68.58 72.39,68.58 | 75.87,64.39 76.2,64.72 76.2,67.94 75.56,68.58 72.39,68.58
  Top 0.61: R100. 56.52,70.74 C64.
N$151
  Top 0.61: 56.52,75.82 D87.
N$152
  Top 0.406: R101. 59.05,76.2 56.52,78.74 D88.
  Top 0.61: R101. 59.05,74.04 | 56.79,81.53 56.79,80.01 56.52,80.01 D88.
N$153
  Top 0.406: R61. 69.85,76.2 67.31,78.74 D50.
  Top 0.61: R61. 69.85,74.04 | 67.59,81.53 67.59,80.01 67.31,80.01 D50.
P  (via drill 0.61 pad 1.02)
  Top 0.406: 70.13,64.39 69.85,64.11 69.85,61.59 67.94,59.69 v62.87,59.69 | T36. 13.34,83.59 13.34,83.82 10.79,83.82 7.62,80.64 7.62,68.58 10.16,66.04 v10.79,66.04 | v12.7,6.35 19.68,13.34 19.68,27.3 19.05,27.94 v19.05,59.69 | v17.14,61.59 R38.
  Bottom 0.406: v62.87,59.69 48.9,59.69 48.26,59.05 22.86,59.05 22.23,59.69 v19.05,59.69 v17.14,61.59 15.24,61.59 v10.79,66.04
  Bottom 1.27: 12.7,1.27 v12.7,6.35
PS0  (via drill 0.61 pad 1.02)
  Top 0.406: 34.57,12.32 34.29,12.04 34.29,10.79 40.64,4.45 v40.64,1.91
  Bottom 1.27: 40.64,1.27 v40.64,1.91 40.64,5.71
PS1  (via drill 0.61 pad 1.02)
  Top 0.406: 46,12.32 45.72,12.04 45.72,9.53 43.18,6.99 v43.18,1.91
  Bottom 1.27: 43.18,1.27 v43.18,1.91 43.18,5.71
PS2  (via drill 0.61 pad 1.02)
  Top 0.406: 53.62,12.32 53.62,9.8 v45.72,1.91
  Bottom 1.27: 45.72,1.27 v45.72,1.91 45.72,5.71
PS3  (via drill 0.61 pad 1.02)
  Top 0.406: v48.26,1.91 54.61,8.26 64.14,8.26 66.04,10.16 67.94,10.16 68.86,11.07 68.86,12.32
  Bottom 1.27: 48.26,1.27 v48.26,1.91 48.26,5.71
SHR  (via drill 0.61 pad 1.02)
  Top 0.406: v35.56,1.91 28.57,8.89 28.57,31.75 27.94,32.38 27.94,53.98 31.75,57.78 31.75,64.11 32.03,64.39
  Bottom 1.27: 35.56,1.27 v35.56,1.91 35.56,5.71
VCC  (via drill 0.61 pad 1.02)
  Top 0.61: 33.02,20.7 v33.02,21.59 C69. | 44.45,20.7 v44.45,21.59 C70. | 28.57,74.04 v28.57,74.93 C77. | 36.2,74.04 v36.2,74.93 C78. | 43.81,74.04 v43.81,74.93 C79. | 53.98,74.04 v53.98,74.93 C80. 51.44,75.82 | 66.67,46.74 v66.67,47.62 C76. | v55.88,47.62 55.88,46.74 | v55.88,47.62 C75. | 44.45,46.74 v44.45,47.62 C74. | 33.02,46.74 v33.02,47.62 C73. | v55.88,21.59 55.88,20.7 | v55.88,21.59 C71. | 66.04,20.7 v66.04,21.59 C72. | 4.45,46.74 v4.45,47.62 C81. | 12.06,46.74 v12.06,47.62 C82. | 5.08,20.7 v5.08,21.59 C83. | 12.7,20.7 v12.7,21.59 C84. | 9.53,74.04 v9.53,74.93 C85. | v19.68,74.93 19.68,74.04 | v19.68,74.93 C86. | 64.77,74.04 v64.77,74.93 C1. | v74.3,47.62 74.3,48.51 | 18.03,74.93 17.14,75.82 | 52.7,22.48 53.59,21.59 v55.88,21.59 | 52.7,48.51 53.59,47.62 v55.88,47.62 | 4.06,61.59 4.06,60.58 v3.81,60.33 4.06,60.07 R28. | 18.03,74.93 17.14,74.04 | v19.68,74.93 18.03,74.93
  Top 0.813: 4.06,35.56 4.06,34.54 v3.81,34.29 4.06,34.04 4.06,33.02
  Bottom 0.813: 10.16,5.08 7.62,5.08 5.08,5.08 2.54,5.08 | 2.54,34.29 v3.81,34.29 | 2.54,60.33 v3.81,60.33
  Bottom 1.27: v64.77,74.93 v53.98,74.93 v43.81,74.93 v36.2,74.93 v28.57,74.93 v19.68,74.93 v9.53,74.93 2.54,74.93 2.54,60.33 2.54,47.62 | v66.04,21.59 v55.88,21.59 v44.45,21.59 v33.02,21.59 v12.7,21.59 v5.08,21.59 2.54,21.59 | 2.54,21.59 2.54,34.29 2.54,47.62 | 2.54,1.27 2.54,5.08 2.54,21.59 | 2.54,47.62 v4.45,47.62 v12.06,47.62 v33.02,47.62 v44.45,47.62 v55.88,47.62 v66.67,47.62 v74.3,47.62 | 5.08,5.08 5.08,1.27 | 7.62,5.08 7.62,1.27 | 10.16,5.08 10.16,1.27
  pour Bottom (isolate 0.356): 1.27,3.17 1.27,76.83 66.67,76.83 66.67,71.75 8.89,71.75 8.89,59.05 2.54,52.7 6.35,48.9 75.56,48.9 75.56,45.09 6.35,45.09 3.81,42.55 3.81,36.83 5.08,35.56 5.08,31.75 3.81,30.48 3.81,23.5 15.24,23.5 16.51,24.77 31.75,24.77 33.02,23.5 67.31,23.5 67.31,18.41 34.29,18.41 31.75,20.95 27.94,20.95 25.4,18.41 3.81,18.41 3.81,8.89 6.99,5.71 10.16,5.71 10.16,3.17
Y  (via drill 0.61 pad 1.02)
  Top 0.406: 12.98,12.32 12.98,9.8 10.79,7.62 10.79,5.08 12.06,3.81 26.04,3.81 v27.94,1.91
  Bottom 1.27: 27.94,1.27 v27.94,1.91 27.94,5.71
Z  (via drill 0.61 pad 1.02)
  Top 0.406: v74.3,18.41 v74.3,24.77 | v75.56,35.56 76.83,35.56 77.47,36.2 77.47,68.58 75.56,70.48 73.03,70.48 71.75,71.75 71.75,82.55 70.48,83.82 68.81,83.82 T72.
  Bottom 0.406: 66.04,5.08 69.85,8.89 74.3,8.89 74.93,9.53 74.93,15.88 74.3,16.51 v74.3,18.41 | v74.3,24.77 73.66,25.4 73.66,33.66 v75.56,35.56
  Bottom 1.27: 66.04,1.27 66.04,5.08

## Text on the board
tNames: /C | /C | C | P | G | /P | /G | P_Inv | SHR | G_Inv | GS0 | GS1 | GS2 | GS3 | G_Mux | 0..3 | PS0 | PS1 | PS2 | PS3 | A_Inv | Y_Inv | P_Mux | /Y | Y | C | /C | SHR | /SHR | PS0 | PS1 | PS2 | PS3 | GS0 | GS1 | GS2 | GS3 | VCC | VCC | VCC | VCC | P | G | /P | /G | /P+1 | D_IN | ALU_A | Z | ALU_Q | GND | GND | GND | GND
